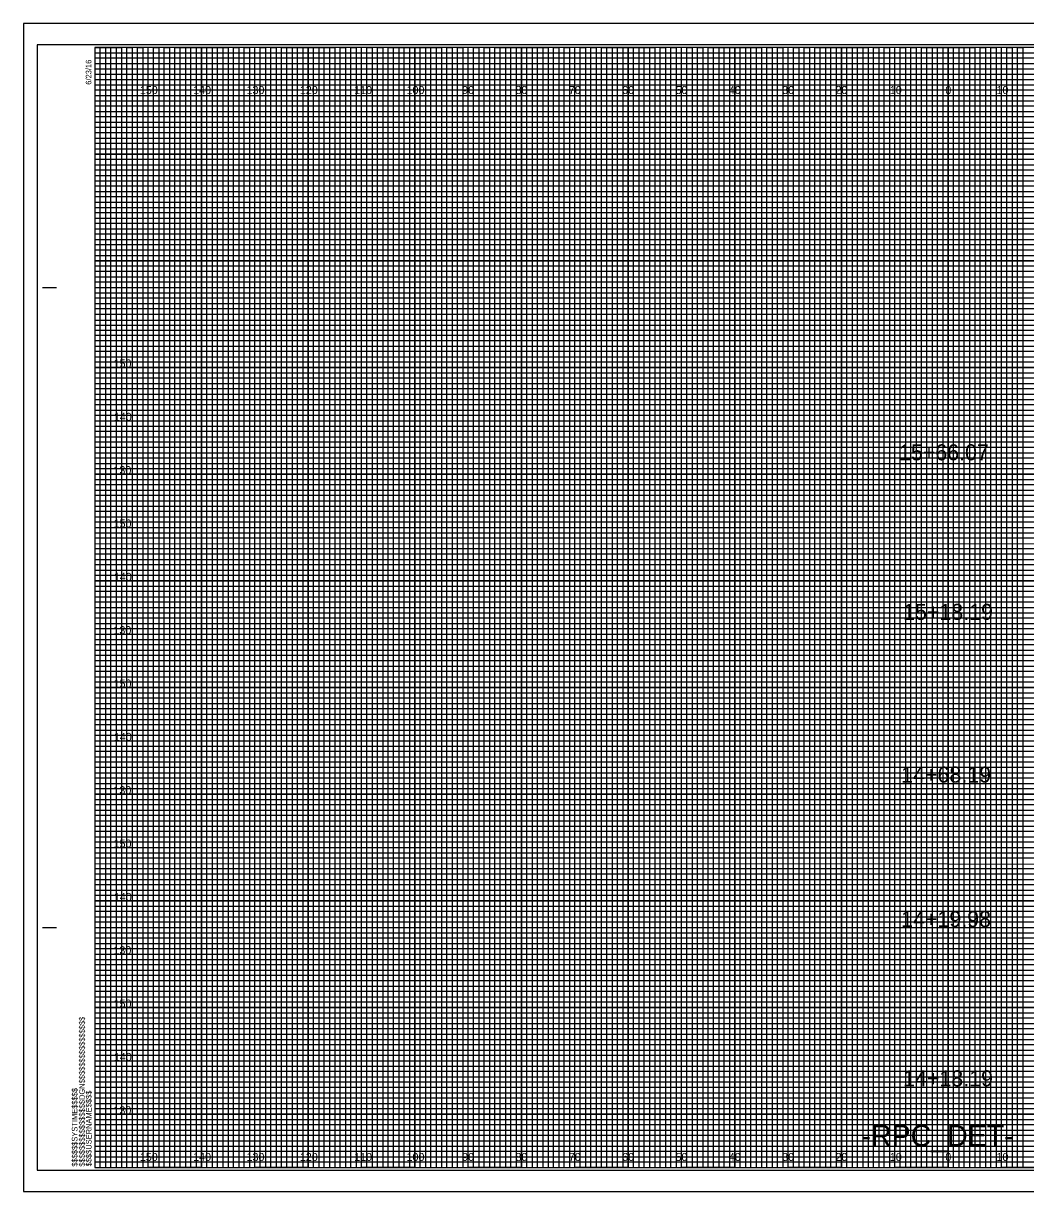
# Model space of a CAD drawing. Extents: x -13 to 323, y -5 to 654.
# Drawn here: x -13.4 to 174.5, y 435.5 to 654.5 of the extents above; entities that cross this region are included whole.
import ezdxf

# ---------------------------------------------------------------- set-up
doc = ezdxf.new("R2010")
doc.units = 0
for name, color, linetype in [('Exist Cross Section Cell', 7, 'Continuous'), ('Exist XS Center Line Elevation Label', 7, 'Continuous'), ('Exist XS Ground Line', 7, 'Continuous'), ('Prop CMT Pvmt Course 1', 7, 'Continuous'), ('Prop CMT Pvmt Course 2', 7, 'Continuous'), ('Prop CMT Pvmt Course 3', 7, 'Continuous'), ('Prop CMT Pvmt Surface', 7, 'Continuous'), ('Prop CMT Pvmt Surface Shoulder', 7, 'Continuous'), ('Prop CMT Shld Paved Course 1', 7, 'Continuous'), ('Prop CMT Shld Paved Course 2', 7, 'Continuous'), ('Prop CMT Shld Paved Course 3', 7, 'Continuous'), ('Prop CMT Slope Grass', 7, 'Continuous'), ('Prop XS Earthwork Shape', 7, 'Continuous')]:
    doc.layers.add(name, color=color, linetype=linetype)

msp = doc.modelspace()

# ---------------------------------------------------------------- linework, layer by layer
at = {"layer": 'Exist XS Center Line Elevation Label'}
for points in [[(0, 650), (5, 650), (5, 440), (15, 440), (15, 650), (25, 650), (25, 440), (35, 440), (35, 650), (45, 650), (45, 440), (55, 440), (55, 650), (65, 650), (65, 440), (75, 440), (75, 650), (85, 650), (85, 440), (95, 440), (95, 650), (105, 650), (105, 440), (115, 440), (115, 650), (125, 650), (125, 440), (135, 440), (135, 650), (145, 650), (145, 440), (155, 440), (155, 650), (165, 650), (165, 440), (175, 440)], [(0, 645), (275, 645)], [(0, 625), (320, 625), (320, 635), (0, 635)], [(0, 605), (320, 605), (320, 615), (0, 615)], [(0, 585), (320, 585), (320, 595), (0, 595)], [(0, 565), (320, 565), (320, 575), (0, 575)], [(0, 545), (320, 545), (320, 555), (0, 555)], [(0, 525), (320, 525), (320, 535), (0, 535)], [(0, 505), (320, 505), (320, 515), (0, 515)], [(0, 485), (320, 485), (320, 495), (0, 495)], [(0, 465), (320, 465), (320, 475), (0, 475)], [(0, 445), (320, 445), (320, 455), (0, 455)]]:
    msp.add_lwpolyline(points, dxfattribs=at)
at = {"layer": 'Exist XS Ground Line'}
for p, q in [((10, 650), (0, 650)), ((10, 440), (10, 650)), ((30, 650), (20, 650)), ((20, 650), (20, 440)), ((30, 440), (30, 650)), ((50, 650), (40, 650)), ((40, 650), (40, 440)), ((50, 440), (50, 650)), ((70, 650), (60, 650)), ((60, 650), (60, 440)), ((70, 440), (70, 650)), ((90, 650), (80, 650)), ((80, 650), (80, 440)), ((90, 440), (90, 650)), ((110, 650), (100, 650)), ((100, 650), (100, 440)), ((110, 440), (110, 650)), ((130, 650), (120, 650)), ((120, 650), (120, 440)), ((130, 440), (130, 650)), ((150, 650), (140, 650)), ((140, 650), (140, 440)), ((150, 440), (150, 650)), ((170, 650), (160, 650)), ((160, 650), (160, 440)), ((170, 440), (170, 650)), ((20, 440), (10, 440)), ((40, 440), (30, 440)), ((60, 440), (50, 440)), ((80, 440), (70, 440)), ((100, 440), (90, 440)), ((120, 440), (110, 440)), ((140, 440), (130, 440)), ((160, 440), (150, 440)), ((180, 440), (170, 440))]:
    msp.add_line(p, q, dxfattribs=at)
for points in [[(0, 640), (320, 640), (320, 630), (0, 630)], [(0, 620), (320, 620), (320, 610), (0, 610)], [(0, 600), (320, 600), (320, 590), (0, 590)], [(0, 580), (320, 580), (320, 570), (0, 570)], [(0, 560), (320, 560), (320, 550), (0, 550)], [(0, 540), (320, 540), (320, 530), (0, 530)], [(0, 520), (320, 520), (320, 510), (0, 510)], [(0, 500), (320, 500), (320, 490), (0, 490)], [(0, 480), (320, 480), (320, 470), (0, 470)], [(0, 460), (320, 460), (320, 450), (0, 450)]]:
    msp.add_lwpolyline(points, dxfattribs=at)
at = {"layer": 'Prop CMT Pvmt Course 1'}
for p, q in [((0, 649), (260, 649)), ((260, 647.98), (0, 647.98)), ((0, 647.98), (0, 647)), ((0, 647), (260, 647)), ((260, 645.89), (0, 645.89)), ((0, 645.89), (0, 644)), ((0, 644), (320, 644))]:
    msp.add_line(p, q, dxfattribs=at)
for points in [[(0, 643), (270, 643), (320, 643), (320, 642), (0, 642)], [(0, 641), (320, 641), (320, 639), (0, 639)], [(0, 638), (320, 638), (320, 637), (0, 636.98)], [(0, 636), (320, 636), (320, 634), (0, 634)], [(0, 633), (320, 633), (320, 632), (0, 632)], [(0, 631), (320, 631), (320, 629), (0, 629)], [(0, 628), (320, 628), (320, 627), (0, 627)], [(0, 626), (320, 626), (320, 624), (0, 624)], [(0, 623), (320, 623), (320, 622), (0, 622)], [(0, 621), (320, 621), (320, 619), (0, 619)], [(0, 618), (320, 618), (320, 617), (0, 617)], [(0, 616), (320, 616), (320, 613.95), (320, 613), (320, 612), (0, 612)], [(0, 614), (320, 614), (320, 613), (0, 613)], [(0, 611), (320, 611), (320, 609), (0, 609.03)], [(0, 609.03), (320, 609), (320, 608), (0, 608)], [(0, 607), (320, 607), (320, 606), (0, 606)], [(0, 604), (320, 604), (320, 603), (0, 603)], [(0, 602), (320, 602), (320, 601), (0, 601)], [(-0.07, 598.89), (320, 598.89), (320, 597.88), (-0.07, 597.88)], [(0, 597), (320, 597), (320, 596), (0, 596)], [(0, 594), (320, 594), (320, 593), (0, 593)], [(0, 592), (320, 592), (320, 591), (0, 591)], [(0, 589), (320, 589), (320, 588), (0, 588)], [(0, 587), (320, 587), (320, 586), (0, 586)], [(0, 584), (320, 584), (320, 583), (0, 583)], [(0, 582), (320, 582), (320, 581), (0, 581)], [(0, 579), (320, 579), (319.99, 577.98), (0, 578)], [(0, 577), (320, 577), (320, 576), (0, 576)], [(0, 574), (320, 574), (320, 573), (0, 573)], [(0, 572), (320, 572), (320, 571), (0, 571)], [(0, 569), (320, 569), (320, 568), (0, 568)], [(0, 567), (320, 567), (320, 566), (0, 566)], [(0, 564), (320, 564), (320, 563), (0, 563)], [(0, 562), (320, 562), (320, 561), (0, 561)], [(0, 559), (320, 559), (320, 558), (0, 558)], [(0, 556.99), (320.07, 556.91), (320, 556), (0, 556)], [(0, 554), (320, 554), (320, 553), (0, 553)], [(0, 552), (320, 552), (320, 551), (0, 551)], [(0, 549), (320, 549), (320, 548), (0, 548)], [(0, 547), (320, 547), (320, 546), (0, 546)], [(0, 544), (320, 544), (320, 543), (0, 543)], [(0, 542), (320, 542), (320, 541), (0, 541)], [(0, 539), (320, 539), (320, 538), (0, 538)], [(0, 537), (320, 537), (320, 536), (0, 536)], [(0, 534), (320, 534), (320, 533), (0, 533)], [(0, 532), (320, 532), (320, 531), (0, 531)], [(0, 529), (320, 529), (320, 528), (0, 528)], [(0, 527), (320, 527), (320, 526), (0, 526)], [(0, 524), (320, 524), (320, 523), (0, 523)], [(0, 522), (320, 522), (320, 521), (0, 521)], [(0, 519), (320, 519), (319.99, 517.98), (0, 518)], [(0, 517), (320, 517), (320, 516), (0, 516)], [(0, 514), (320, 514), (320, 513), (0, 513)], [(0, 512), (320, 512), (320, 511), (0, 511)], [(0, 509), (320, 509), (320, 508), (0, 508)], [(0, 507), (320, 507), (320, 506), (0, 506)], [(0, 504), (320, 504), (320, 503), (0, 503)], [(0, 502), (320, 502), (320, 501), (0, 501)], [(0, 499), (320, 499), (320, 498), (0, 498)], [(0, 496.99), (320.07, 496.91), (320, 496), (0, 496)], [(0, 494), (320, 494), (320, 493), (0, 493)], [(0, 492), (320, 492), (320, 491), (0, 491)], [(0, 489), (320, 489), (320, 488), (0, 488)], [(0, 487), (320, 487), (320, 486), (0, 486)], [(0, 484), (320, 484), (320, 483), (0, 483)], [(0, 482), (320, 482), (320, 481), (0, 481)], [(0, 479), (320, 479), (320, 478), (0, 478)], [(0, 477), (320, 477), (320, 476), (0, 476)], [(0, 474), (320, 474), (320, 473), (0, 473)], [(0, 472), (320, 472), (320, 471), (0, 471)], [(0, 469), (320, 469), (320, 468), (0, 468)], [(0, 467), (320, 467), (320, 466), (0, 466)], [(0, 464), (320, 464), (320, 463), (0, 463)], [(0, 462), (320, 462), (320, 461), (0, 461)], [(0, 459), (320, 459), (320, 458), (0, 458)], [(0, 457), (320, 457), (320, 456), (0, 456)], [(0, 454), (320, 454), (320, 453), (0, 453)], [(0, 452), (320, 452), (320, 451), (0, 451)], [(0, 449), (320, 449), (320, 448), (0, 448)], [(0, 447), (320, 447), (320, 446), (0, 446)], [(0, 444), (320, 444), (320, 443), (0, 443)], [(0, 442), (320, 442), (320, 441), (0, 441)]]:
    msp.add_lwpolyline(points, dxfattribs=at)
at = {"layer": 'Prop CMT Pvmt Surface'}
for points in [[(0, 440), (1, 440), (1, 650), (2, 650), (2, 440)], [(2, 440), (3, 440), (3, 650), (4, 650), (4, 440)], [(5, 440), (6, 440), (6, 650), (7, 650), (7, 440)], [(7, 440), (8, 440), (8, 650), (9, 650), (9, 440)], [(10, 440), (11, 440), (11, 650), (12, 650), (12, 440)], [(12, 440), (13, 440), (13, 650), (14, 650), (14, 440)], [(15, 440), (16, 440), (16, 650), (17, 650), (17, 440)], [(17, 440), (18, 440), (18, 650), (19, 650), (19, 440)], [(20, 440), (21, 440), (21, 650), (22, 650), (22, 440)], [(22, 440), (23, 440), (23, 650), (24, 650), (24, 440)], [(25, 440), (26, 440), (26, 650), (27, 650), (27, 440)], [(27, 440), (28, 440), (28, 650), (29, 650), (29, 440)], [(30, 440), (31, 440), (31, 650), (32, 650), (32, 440)], [(32, 440), (33, 440), (33, 650), (34, 650), (34, 440)], [(35, 440), (36, 440), (36, 650), (37, 650), (37, 440)], [(37, 440), (38, 440), (38, 650), (39, 650), (39, 440)], [(40, 440), (41, 440), (41, 650), (42, 650), (42, 440)], [(42, 440), (43, 440), (43, 650), (44, 650), (44, 440)], [(45, 440), (46, 440), (46, 650), (47, 650), (47, 440)], [(47, 440), (48, 440), (48, 650), (49, 650), (49, 440)], [(50, 440), (51, 440), (51, 650), (52, 650), (52, 440)], [(52, 440), (53, 440), (53, 650), (54, 650), (54, 440)], [(55, 440), (56, 440), (56, 650), (57, 650), (57, 440)], [(57, 440), (58, 440), (58, 650), (59, 650), (59, 440)], [(60, 440), (61, 440), (61, 650), (62, 650), (62, 440)], [(62, 440), (63, 440), (63, 650), (64, 650), (64, 440)], [(65, 440), (66, 440), (66, 650), (67, 650), (67, 440)], [(67, 440), (68, 440), (68, 650), (69, 650), (69, 440)], [(70, 440), (71, 440), (71, 650), (72, 650), (72, 440)], [(72, 440), (73, 440), (73, 650), (74, 650), (74, 440)], [(75, 440), (76, 440), (76, 650), (77, 650), (77, 440)], [(77, 440), (78, 440), (78, 650), (79, 650), (79, 440)], [(80, 440), (81, 440), (81, 650), (82, 650), (82, 440)], [(82, 440), (83, 440), (83, 650), (84, 650), (84, 440)], [(85, 440), (86, 440), (86, 650), (87, 650), (87, 440)], [(87, 440), (88, 440), (88, 650), (89, 650), (89, 440)], [(90, 440), (91, 440), (91, 650), (92, 650), (92, 440)], [(92, 440), (93, 440), (93, 650), (94, 650), (94, 440)], [(95, 440), (96, 440), (96, 650), (97, 650), (97, 440)], [(97, 440), (98, 440), (98, 650), (99, 650), (99, 440)], [(100, 440), (101, 440), (101, 650), (102, 650), (102, 440)], [(102, 440), (103, 440), (103, 650), (104, 650), (104, 440)], [(105, 440), (106, 440), (106, 650), (107, 650), (107, 440)], [(107, 440), (108, 440), (108, 650), (109, 650), (109, 440)], [(110, 440), (111, 440), (111, 650), (112, 650), (112, 440)], [(112, 440), (113, 440), (113, 650), (114, 650), (114, 440)], [(115, 440), (116, 440), (116, 650), (117, 650), (117, 440)], [(117, 440), (118, 440), (118, 650), (119, 650), (119, 440)], [(120, 440), (121, 440), (121, 650), (122, 650), (122, 440)], [(122, 440), (123, 440), (123, 650), (124, 650), (124, 440)], [(125, 440), (126, 440), (126, 650), (127, 650), (127, 440)], [(127, 440), (128, 440), (128, 650), (129, 650), (129, 440)], [(130, 440), (131, 440), (131, 650), (132, 650), (132, 440)], [(132, 440), (133, 440), (133, 650), (134, 650), (134, 440)], [(135, 440), (136, 440), (136, 650), (137, 650), (137, 440)], [(137, 440), (138, 440), (138, 650), (139, 650), (139, 440)], [(140, 440), (141, 440), (141, 650), (142, 650), (142, 440)], [(142, 440), (143, 440), (143, 650), (144, 650), (144, 440)], [(145, 440), (146, 440), (146, 650), (147, 650), (147, 440)], [(147, 440), (148, 440), (148, 650), (149, 650), (149, 440)], [(150, 440), (151, 440), (151, 650), (152, 650), (152, 440)], [(152, 440), (153, 440), (153, 650), (154, 650), (154, 440)], [(155, 440), (156, 440), (156, 650), (157, 650), (157, 440)], [(157, 440), (158, 440), (158, 650), (159, 650), (159, 440)], [(160, 440), (161, 440), (161, 650), (162, 650), (162, 440)], [(162, 440), (163, 440), (163, 650), (164, 650), (164, 440)], [(165, 440), (166, 440), (166, 650), (167, 650), (167, 440)], [(167, 440), (168, 440), (168, 650), (169, 650), (169, 440)], [(170, 440), (171, 440), (171, 650), (172, 650), (172, 440)], [(172, 440), (173, 440), (173, 650), (174, 650), (174, 440)]]:
    msp.add_lwpolyline(points, dxfattribs=at)
at = {"layer": 'Prop CMT Shld Paved Course 1'}
msp.add_lwpolyline([(-10.8, 439.5), (322.4, 439.5), (322.4, 650.5), (-10.8, 650.5)], close=True, dxfattribs=at)
at = {"layer": 'Prop CMT Shld Paved Course 2'}
for p, q in [((10, 440), (10, 650)), ((20, 440), (20, 650)), ((30, 440), (30, 650)), ((40, 440), (40, 650)), ((50, 440), (50, 650)), ((60, 440), (60, 650)), ((70, 440), (70, 650)), ((80, 440), (80, 650)), ((90, 440), (90, 650)), ((100, 440), (100, 650)), ((110, 440), (110, 650)), ((120, 440), (120, 650)), ((130, 440), (130, 650)), ((140, 440), (140, 650)), ((150, 440), (150, 650)), ((160, 440), (160, 650)), ((170, 440), (170, 650)), ((0, 640), (320, 640)), ((0, 630), (320, 630)), ((0, 620), (320, 620)), ((0, 610), (320, 610)), ((0, 600), (320, 600)), ((0, 590), (320, 590)), ((0, 580), (320, 580)), ((0, 570), (320, 570)), ((0, 560), (320, 560)), ((0, 550), (320, 550)), ((0, 540), (320, 540)), ((0, 530), (320, 530)), ((0, 520), (320, 520)), ((0, 510), (320, 510)), ((0, 500), (320, 500)), ((0, 490), (320, 490)), ((0, 480), (320, 480)), ((0, 470), (320, 470)), ((0, 460), (320, 460)), ((0, 450), (320, 450))]:
    msp.add_line(p, q, dxfattribs=at)
at = {"layer": 'Prop CMT Shld Paved Course 3'}
for p, q in [((323.3, 654.5), (-13.4, 654.5)), ((-13.4, 654.5), (-13.4, 435.5)), ((-13.4, 435.5), (323.3, 435.5))]:
    msp.add_line(p, q, dxfattribs=at)
at = {"layer": 'Prop CMT Slope Grass'}
for p, q in [((-9.8, 605), (-7.3, 605)), ((-9.7, 605), (-7.2, 605)), ((-9.8, 485), (-7.3, 485)), ((-9.7, 485), (-7.2, 485)), ((0, 440), (0, 440)), ((0, 440), (0, 440)), ((0, 440), (0, 440)), ((0, 440), (0, 440)), ((0, 440), (0, 440)), ((0, 440), (0, 440)), ((0, 440), (0, 440))]:
    msp.add_line(p, q, dxfattribs=at)
msp.add_lwpolyline([(320, 650), (0, 650), (0, 440), (320, 440)], close=True, dxfattribs=at)
at = {"layer": 'Prop XS Earthwork Shape'}
msp.add_lwpolyline([(-13.4, 435.5), (323.3, 435.5), (323.3, 654.5), (-13.4, 654.5)], close=True, dxfattribs=at)

# ---------------------------------------------------------------- texts
at = {"layer": 'Exist Cross Section Cell'}
for s, p in [('150', (8.44, 641.25)), ('140', (18.44, 641.25)), ('130', (28.44, 641.25)), ('120', (38.44, 641.25)), ('110', (48.62, 641.25)), ('100', (58.44, 641.25)), ('90', (68.86, 641.25)), ('80', (78.86, 641.25)), ('70', (88.86, 641.25)), ('60', (98.86, 641.25)), ('50', (108.86, 641.25)), ('40', (118.86, 641.25)), ('30', (128.86, 641.25)), ('20', (138.86, 641.25)), ('10', (149.04, 641.25)), ('0', (159.45, 641.25)), ('0', (159.45, 641.25)), ('10', (169.04, 641.25)), ('150', (8.44, 441.25)), ('140', (18.44, 441.25)), ('130', (28.44, 441.25)), ('120', (38.44, 441.25)), ('110', (48.62, 441.25)), ('100', (58.44, 441.25)), ('90', (68.86, 441.25)), ('80', (78.86, 441.25)), ('70', (88.86, 441.25)), ('60', (98.86, 441.25)), ('50', (108.86, 441.25)), ('40', (118.86, 441.25)), ('30', (128.86, 441.25)), ('20', (138.86, 441.25)), ('10', (149.04, 441.25)), ('0', (159.45, 441.25)), ('0', (159.45, 441.25)), ('10', (169.04, 441.25))]:
    msp.add_text(s, height=1.5, dxfattribs=at).set_placement(p)
at = {"layer": 'Prop CMT Pvmt Course 2'}
for s, p in [('150', (3.52, 590)), ('140', (3.57, 580)), ('130', (3.49, 570)), ('150', (3.52, 560)), ('140', (3.57, 550)), ('130', (3.49, 540)), ('150', (3.52, 530)), ('140', (3.57, 520)), ('130', (3.49, 510)), ('150', (3.52, 500)), ('140', (3.57, 490)), ('130', (3.49, 480)), ('150', (3.52, 470)), ('140', (3.57, 460)), ('130', (3.49, 450))]:
    msp.add_text(s, height=1.5, dxfattribs=at).set_placement(p)
at = {"layer": 'Prop CMT Pvmt Course 3'}
for s, p in [('15+66.07', (150.76, 572.59)), ('15+18.19', (151.53, 542.68)), ('14+68.19', (151.17, 512.18)), ('14+19.98', (151.16, 485.1)), ('14+18.19', (151.53, 455.24))]:
    msp.add_text(s, height=3, dxfattribs=at).set_placement(p)
at = {"layer": 'Prop CMT Pvmt Surface Shoulder'}
msp.add_text('-RPC_DET-', height=4, dxfattribs=at).set_placement((143.73, 444))
at = {"layer": 'Prop CMT Slope Grass'}
for s, p in [('6/23/16', (-0.65, 643)), ('$$$$$$$$$$$$$$$$DGN$$$$$$$$$$$$$$$$', (-1.88, 440.18)), ('$$$$$$SYSTIME$$$$$', (-3.26, 440.18)), ('$$$$USERNAME$$$$', (-0.62, 440.23))]:
    msp.add_text(s, height=1.05, rotation=90, dxfattribs=at).set_placement(p)

doc.saveas('drawing.dxf')
